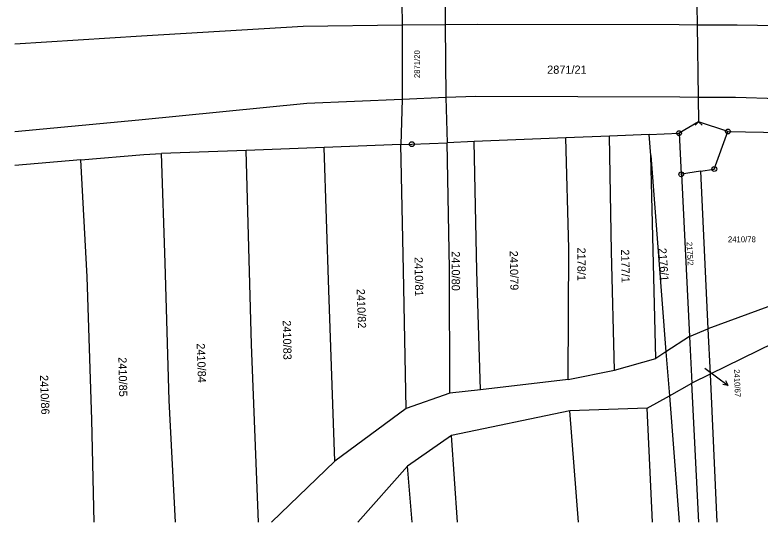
# Model space of a CAD drawing. Extents: x -516758 to -516441, y -1129775 to -1129534.
# Drawn here: x -516754.5 to -516599.6, y -1129774.7 to -1129669.3 of the extents above; entities that cross this region are included whole.
import ezdxf

# ---------------------------------------------------------------- set-up
doc = ezdxf.new("R2010")
doc.units = 0
for name, color, linetype in [('Vrstva 1', 7, 'Continuous'), ('Vrstva 14', 7, 'Continuous'), ('Vrstva 2', 7, 'Continuous'), ('Vrstva 7', 7, 'Continuous'), ('Vrstva 8', 7, 'Continuous')]:
    doc.layers.add(name, color=color, linetype=linetype)

msp = doc.modelspace()

# ---------------------------------------------------------------- linework, layer by layer
at = {"layer": 'Vrstva 1'}
for p, q in [((-516640.02, -1129694.83), (-516659.04, -1129695.61)), ((-516630.89, -1129694.45), (-516640.02, -1129694.83)), ((-516622.69, -1129694.11), (-516630.89, -1129694.45)), ((-516674.27, -1129696.24), (-516690.22, -1129696.84)), ((-516659.04, -1129695.61), (-516664.68, -1129695.85)), ((-516706.47, -1129697.46), (-516724.07, -1129698.12)), ((-516690.22, -1129696.84), (-516706.47, -1129697.46)), ((-516740.81, -1129699.41), (-516754.51, -1129700.61)), ((-516611.99, -1129701.77), (-516615.95, -1129702.4)), ((-516615.95, -1129702.4), (-516614.28, -1129736.16)), ((-516611.99, -1129701.77), (-516610.45, -1129734.53)), ((-516594.58, -1129728.7), (-516610.45, -1129734.53)), ((-516614.28, -1129736.16), (-516610.45, -1129734.53)), ((-516610.45, -1129734.53), (-516610.01, -1129743.98)), ((-516614.28, -1129736.16), (-516613.8, -1129745.82)), ((-516596.79, -1129737.54), (-516610.01, -1129743.98)), ((-516629.84, -1129743.12), (-516621.26, -1129740.68)), ((-516639.53, -1129745.05), (-516629.84, -1129743.12)), ((-516610.01, -1129743.98), (-516613.8, -1129745.82)), ((-516639.53, -1129745.05), (-516657.75, -1129747.2)), ((-516657.75, -1129747.2), (-516664.12, -1129747.89)), ((-516664.12, -1129747.89), (-516673.17, -1129751.09)), ((-516673.17, -1129751.09), (-516688.01, -1129762.05)), ((-516639.14, -1129751.59), (-516663.73, -1129756.7)), ((-516623.07, -1129751.02), (-516639.14, -1129751.59)), ((-516663.73, -1129756.7), (-516672.93, -1129763.05)), ((-516688.01, -1129762.05), (-516701.18, -1129774.71)), ((-516672.93, -1129763.05), (-516683.23, -1129774.71))]:
    msp.add_line(p, q, dxfattribs=at)
for points in [[(-516674.14, -1129662.14), (-516674.04, -1129671.36), (-516674.04, -1129686.87), (-516674.27, -1129696.24)], [(-516665.06, -1129661.63), (-516665.07, -1129671.25), (-516664.94, -1129686.47), (-516664.68, -1129695.85)], [(-516639.53, -1129745.05), (-516639.35, -1129717.86), (-516640.02, -1129694.83)], [(-516629.84, -1129743.12), (-516630.46, -1129718.43), (-516630.89, -1129694.45)], [(-516622.69, -1129694.11), (-516616.45, -1129693.85), (-516616, -1129702.41), (-516615.95, -1129702.4)], [(-516621.26, -1129740.68), (-516622.35, -1129698.49), (-516622.69, -1129694.11)], [(-516611.99, -1129701.77), (-516609.13, -1129701.31), (-516606.29, -1129693.51), (-516602.64, -1129693.59), (-516595.13, -1129693.75)], [(-516674.27, -1129696.24), (-516672, -1129696.15), (-516664.68, -1129695.85)], [(-516673.17, -1129751.09), (-516673.72, -1129722.43), (-516674.27, -1129696.24)], [(-516664.12, -1129747.89), (-516664.19, -1129722), (-516664.68, -1129695.85)], [(-516657.75, -1129747.2), (-516658.48, -1129722.51), (-516659.04, -1129695.61)], [(-516703.87, -1129774.71), (-516705.31, -1129737.81), (-516706.47, -1129697.46)], [(-516688.01, -1129762.05), (-516689.24, -1129726.52), (-516690.22, -1129696.84)], [(-516740.81, -1129699.41), (-516727.72, -1129698.26), (-516724.07, -1129698.12)], [(-516738, -1129774.71), (-516738.55, -1129753.42), (-516739.47, -1129723.74), (-516740.81, -1129699.41)], [(-516721.14, -1129774.71), (-516722.42, -1129749.45), (-516723.27, -1129720.84), (-516724.07, -1129698.12)], [(-516614.28, -1129736.16), (-516619.17, -1129739.32), (-516621.26, -1129740.68)], [(-516610.01, -1129743.98), (-516608.58, -1129774.71)], [(-516623.07, -1129751.02), (-516618.46, -1129748.44), (-516613.8, -1129745.82)], [(-516612.37, -1129774.71), (-516613.8, -1129745.82)], [(-516637.36, -1129774.71), (-516639.14, -1129751.59)], [(-516621.94, -1129774.71), (-516623.07, -1129751.02)], [(-516662.52, -1129774.71), (-516663.73, -1129756.7)], [(-516671.94, -1129774.71), (-516672.93, -1129763.05)]]:
    msp.add_lwpolyline(points, dxfattribs=at)
at = {"layer": 'Vrstva 2'}
for p, q in [((-516612.74, -1129667.33), (-516612.68, -1129671.31)), ((-516728.18, -1129673.6), (-516694.58, -1129671.62)), ((-516694.58, -1129671.62), (-516674.04, -1129671.36)), ((-516674.04, -1129671.36), (-516665.07, -1129671.25)), ((-516665.07, -1129671.25), (-516658.35, -1129671.17)), ((-516658.35, -1129671.17), (-516616.45, -1129671.29)), ((-516616.45, -1129671.29), (-516612.68, -1129671.31)), ((-516612.68, -1129671.31), (-516608.92, -1129671.32)), ((-516612.68, -1129671.31), (-516612.46, -1129686.43)), ((-516608.92, -1129671.32), (-516604.38, -1129671.33)), ((-516604.38, -1129671.33), (-516552.67, -1129672.11)), ((-516754.51, -1129675.32), (-516728.18, -1129673.6)), ((-516674.04, -1129686.87), (-516693.8, -1129687.71)), ((-516664.94, -1129686.47), (-516674.04, -1129686.87)), ((-516658.69, -1129686.21), (-516664.94, -1129686.47)), ((-516616.29, -1129686.41), (-516658.69, -1129686.21)), ((-516612.46, -1129686.43), (-516616.29, -1129686.41)), ((-516608.63, -1129686.45), (-516612.46, -1129686.43)), ((-516612.46, -1129686.43), (-516612.39, -1129691.49)), ((-516604.73, -1129686.47), (-516608.63, -1129686.45)), ((-516553.22, -1129687.95), (-516604.73, -1129686.47)), ((-516693.8, -1129687.71), (-516728.78, -1129691.13)), ((-516728.78, -1129691.13), (-516754.51, -1129693.56)), ((-516612.39, -1129691.49), (-516616.45, -1129693.85)), ((-516613.09, -1129692.21), (-516612.39, -1129691.49)), ((-516606.29, -1129693.51), (-516612.39, -1129691.49)), ((-516611.67, -1129692.19), (-516612.39, -1129691.49)), ((-516622.35, -1129698.49), (-516619.17, -1129739.32)), ((-516619.17, -1129739.32), (-516618.46, -1129748.44)), ((-516618.46, -1129748.44), (-516616.41, -1129774.71))]:
    msp.add_line(p, q, dxfattribs=at)
at = {"layer": 'Vrstva 7'}
for p, q in [((-516611.06, -1129742.72), (-516608.65, -1129744.51)), ((-516608.65, -1129744.51), (-516606.25, -1129746.32)), ((-516606.25, -1129746.32), (-516606.75, -1129745.31)), ((-516606.25, -1129746.32), (-516607.35, -1129746.11))]:
    msp.add_line(p, q, dxfattribs=at)
at = {"layer": 'Vrstva 8'}
for centre, radius in [((-516606.29, -1129693.51), 0.5), ((-516616.45, -1129693.85), 0.5), ((-516616.45, -1129693.85), 0.0303), ((-516606.29, -1129693.51), 0.0303), ((-516672, -1129696.15), 0.5), ((-516672, -1129696.15), 0.0303), ((-516609.13, -1129701.31), 0.5), ((-516616, -1129702.41), 0.5), ((-516616, -1129702.41), 0.0303), ((-516609.13, -1129701.31), 0.0303)]:
    msp.add_circle(centre, radius, dxfattribs=at)

# ---------------------------------------------------------------- texts
at = {"layer": 'Vrstva 14'}
for s, height, rotation, p in [('2871/20', 1.2, 90, (-516670.31, -1129682.41)), ('2175/2', 1.2, 273, (-516614.9, -1129716.5)), ('2178/1', 1.7, 270, (-516637.58, -1129717.64)), ('2176/1', 1.7, 274, (-516620.78, -1129717.79)), ('2410/80', 1.7, 270, (-516663.71, -1129718.41)), ('2410/79', 1.7, 271, (-516651.66, -1129718.32)), ('2177/1', 1.7, 271, (-516628.51, -1129718.04)), ('2410/81', 1.7, 271, (-516671.44, -1129719.62)), ('2410/82', 1.7, 272, (-516683.47, -1129726.25)), ('2410/83', 1.7, 271, (-516698.83, -1129732.77)), ('2410/84', 1.7, 272, (-516716.73, -1129737.57)), ('2410/85', 1.7, 271, (-516732.99, -1129740.45)), ('2410/86', 1.7, 272, (-516749.3, -1129744.18)), ('2410/67', 1.2, 272, (-516605.04, -1129742.96))]:
    msp.add_text(s, height=height, rotation=rotation, dxfattribs=at).set_placement(p)
for s, height, p in [('2871/21', 1.7, (-516643.87, -1129681.51)), ('2410/78', 1.2, (-516606.29, -1129716.53))]:
    msp.add_text(s, height=height, dxfattribs=at).set_placement(p)

doc.saveas('drawing.dxf')
